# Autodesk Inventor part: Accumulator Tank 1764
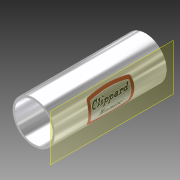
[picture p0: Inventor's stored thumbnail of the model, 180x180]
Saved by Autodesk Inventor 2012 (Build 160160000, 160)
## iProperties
Created: 2010-01
Part Number: Accumulator Tank 1764
Document SubType Name: Modeling
Designer: cmcfadden
Density: 1 g/cm^3
Material: Default
Author: cmcfadden
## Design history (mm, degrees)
sketch "Sketch1"
  geometry: C1 r 26.416 at (10.426, -13.014); 1 further point
  constraints: 1 centre point
  dimensions: "d0" = 52.832 diameter of C1
extrude "Extrusion1" new body sketch "Sketch1" distance "d1" = 139.7508; taper "d2" = 0 deg
workplane "Work Plane1"
sketch "Sketch2"
  geometry: 1 further point
sketch "Sketch3"
  geometry: C1 r 26.416 at (0, 0) reference; C2 r 23.647 at (0, 0); 1 further point
  constraints: 1 centre point, 1 coincident
  dimensions: "d14" = 47.2948 diameter of C2
extrude "Extrusion2" cut sketch "Sketch3" stored distance "d15" = 25.4; taper "d16" = 0 deg
sketch "Sketch4"
  geometry: L1 (-39.43, 139.751)-(13.402, 139.751) reference; L2 (-39.43, 0)-(13.402, 0) reference; L3 (13.402, 0)-(13.402, 139.751) reference; L4 (-39.43, 0)-(-39.43, 139.751) reference; L5 (6.384, 98.821)-(6.384, 39.29); L6 (6.384, 39.29)-(-32.245, 39.29); L7 (-32.245, 39.29)-(-32.245, 98.821); L8 (-32.245, 98.821)-(6.384, 98.821); 1 further point; 1 other entity
  constraints: 2 other
feature "Decal1" sketch "Sketch4"
body "Solid1"
node "Projected Loop1"
node "Image5"
other parameters: "d3" = 38.1
